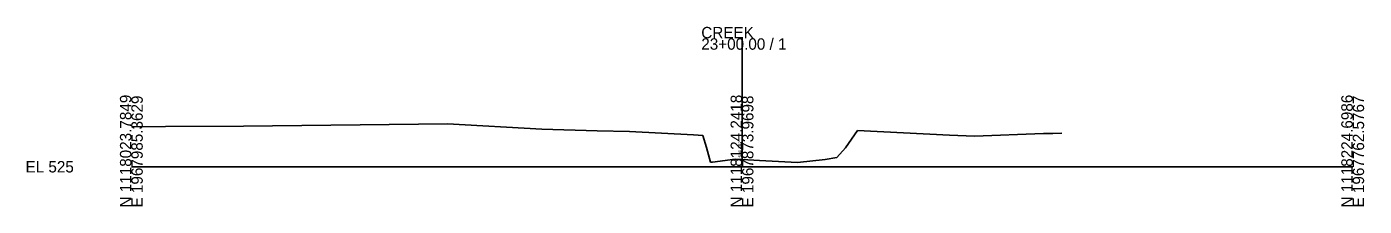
# Model space of a CAD drawing. Extents: x 9974 to 10303, y 9990 to 19550.
# Drawn here: x 9974.3 to 10302.8, y 12490.3 to 12534.4 of the extents above; entities that cross this region are included whole.
import ezdxf

# ---------------------------------------------------------------- set-up
doc = ezdxf.new("R2010")
doc.units = 0
for name, color, linetype in [('Level 10', 7, 'Continuous'), ('Level 60', 7, 'Continuous'), ('Level 63', 7, 'Continuous')]:
    doc.layers.add(name, color=color, linetype=linetype)

msp = doc.modelspace()

# ---------------------------------------------------------------- linework, layer by layer
at = {"layer": 'Level 60'}
for p, q in [((10000, 12509.83), (10008.38, 12509.9)), ((10008.38, 12509.9), (10027.55, 12510)), ((10027.55, 12510), (10077.65, 12510.51)), ((10077.65, 12510.51), (10100.82, 12509.27)), ((10100.82, 12509.27), (10114.39, 12508.83)), ((10114.39, 12508.83), (10122.4, 12508.67)), ((10122.4, 12508.67), (10138.07, 12507.8)), ((10138.07, 12507.8), (10140.38, 12507.7)), ((10140.38, 12507.7), (10141.25, 12504.72)), ((10175.39, 12504.67), (10178.38, 12508.88)), ((10178.38, 12508.88), (10200.98, 12507.73)), ((10200.98, 12507.73), (10207.13, 12507.51)), ((10207.13, 12507.51), (10224.07, 12508.15)), ((10224.07, 12508.15), (10226.33, 12508.2)), ((10226.33, 12508.2), (10228.52, 12508.23)), ((10141.25, 12504.72), (10142.29, 12501.13)), ((10173.26, 12502.3), (10175.39, 12504.67)), ((10142.29, 12501.13), (10142.72, 12501.13)), ((10142.72, 12501.13), (10148.28, 12501.89)), ((10148.28, 12501.89), (10150, 12501.78)), ((10150, 12501.78), (10154.29, 12501.5)), ((10154.29, 12501.5), (10163.62, 12501.01)), ((10163.62, 12501.01), (10170.4, 12501.76)), ((10170.4, 12501.76), (10173.26, 12502.3))]:
    msp.add_line(p, q, dxfattribs=at)
at = {"layer": 'Level 63'}
for p, q in [((10150, 12500), (10150, 12531.54)), ((10000, 12500), (10150, 12500)), ((10150, 12500), (10300, 12500))]:
    msp.add_line(p, q, dxfattribs=at)

# ---------------------------------------------------------------- texts
at = {"layer": 'Level 10'}
msp.add_text('526.782', height=0.8, rotation=90, dxfattribs=at).set_placement((10149.9, 12502.28))
at = {"layer": 'Level 63'}
for s, p in [('CREEK', (10140, 12531.54)), ('23+00.00 / 1', (10140, 12528.74)), ('EL 525', (9974, 12498.6))]:
    msp.add_text(s, height=2.8, dxfattribs=at).set_placement(p)
for s, p in [('N 1118023.7849', (10000, 12490)), ('E 1967985.3629', (10002.8, 12490)), ('N 1118124.2418', (10150, 12490)), ('E 1967873.9698', (10152.8, 12490)), ('N 1118224.6986', (10300, 12490)), ('E 1967762.5767', (10302.8, 12490))]:
    msp.add_text(s, height=2.8, rotation=90, dxfattribs=at).set_placement(p)

doc.saveas('drawing.dxf')
